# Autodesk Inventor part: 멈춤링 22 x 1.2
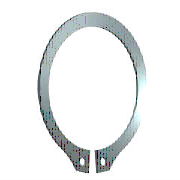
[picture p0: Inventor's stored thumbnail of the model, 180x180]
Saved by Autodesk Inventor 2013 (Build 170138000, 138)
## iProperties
IsCustomPart: 0
Created: 2015-11
Part Number: 멈춤링 22 x 1.2
Material: 스테인리스강
Description: 리테이닝 링(C형)
Document SubType Name: Modeling
Standard: KS B 1336
Designer: mdu
Standards Organization: KS
Language: ko-KR
Size Designation: 22 x 1.2
Categories: <MemberInstance><Categories><Category DisplayName="샤프트 부품" InternalName="7f7aeb1f-a693-4053-b835-cee3144e0d98" Mnemonic="SHFT"><Category DisplayName="써클립" Inter
Density: 8.08 g/cm^3
Mass: 1.87978 g
Surface Area: 5.91219 cm^2
Volume: 0.232646 cm^3
Author: mdu
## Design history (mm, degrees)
sketch "스케치1"
  geometry: L1 (-6, 0)-(6, 0) reference; L2 (0, 20.189)-(0, -80.536) reference; L3 (-48.09, 0)-(48.09, 0) reference; L4 (-0.5, -21.488)-(-0.5, -25.588); L5 (-0.5, -6.54)-(-0.5, -13.29); L6 (-2.795, 2.7)-(3.672, 2.7); L7 (0.5, -6.54)-(0.5, -13.29); L8 (0.5, -21.488)-(0.5, -25.588); C1 r 1 at (-2, -23.437); C2 r 1 at (2, -23.437); A1 r 10.5 centre (0, -11) between (0.5, -21.488) and (-0.5, -21.488); A2 r 13.025 centre (0, -10.325) between (5.149, -22.289) and (-5.149, -22.289); A3 r 14.597 centre (0, -11) between (-2.318, -25.411) and (-0.5, -25.588); A4 r 2 centre (-2, -23.437) between (-3.97, -23.781) and (-2.318, -25.411); A5 r 2 centre (-5.94, -24.126) between (-3.97, -23.781) and (-5.149, -22.289); A6 r 2 centre (5.94, -24.126) between (5.149, -22.289) and (3.97, -23.781); A7 r 2 centre (2, -23.437) between (2.318, -25.411) and (3.97, -23.781); A8 r 14.597 centre (0, -11) between (0.5, -25.588) and (2.318, -25.411)
  constraints: 16 point on circle, 12 end point, 10 centre point, 9 symmetric about line, 5 point on line, 4 tangent, 3 coincident, 2 horizontal, 1 perpendicular, 1 vertical, 5 other
  dimensions: "d0" = 21 diameter of A1 (= ND); "d1" = 4.1 distance of L4.end L4.start (= SRB2); "d6" = 0.5 distance between parallel lines of L2 L5 (= 0.25 x SD5); "d7" = 2.7 distance between parallel lines of L6 L3 (= SRB1); "d8" = 0.675 distance of A1.centre A2.centre (= 0.25 x SRB1); "d9" = 2 radius of A4 (= SD5); "d10" = 2 radius of A5 (= SD5); "d11" = 1.5 distance from line of L4 A4.centre (= 0.75 x SD5); "d12" = 2 diameter of C1 (= SD5); "d13" = 2 diameter of C2 (= SD5); "d14" = 11 distance from line of A1.centre L1 (= 0.5 x WD)
extrude "본체" new body sketch "스케치1" distance "d2" = 1.2 (= SD); taper "d3" = 0 deg
workaxis "Work Axis1"
workplane "Work Plane1"
body "Solid1"
other parameters: "WD" = 22 (= WDMIN) [user parameter; used in 1 equation term], "SD" = 1.2 [user parameter; used in 1 equation term], "SRB1" = 2.7 [user parameter; used in 2 equation terms], "ND" = 21 [user parameter; used in 1 equation term], "SRB2" = 4.1 [user parameter; used in 1 equation term], "SD5" = 2 [user parameter; used in 6 equation terms], "d15" = 0, "d16" = 0, "d17" = 0, "d41" = 0, "d42" = 0, "WDMIN" = 22 [user parameter; used in 1 equation term], "SD3" = 20.5 [user parameter], "WDMAX" = 24 [user parameter]
